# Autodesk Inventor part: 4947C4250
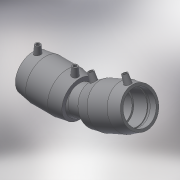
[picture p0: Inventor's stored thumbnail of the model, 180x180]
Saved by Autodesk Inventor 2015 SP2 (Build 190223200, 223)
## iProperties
Created: 2017-06
Part Number: 4947C4250
Material: Generic
Description: PLASSON ADJUSTABLE ELBOW 250
Document SubType Name: Modeling
Designer: KIM
Mass: 55.0731 g
Surface Area: 148.067 cm^2
Volume: 55.0731 cm^3
Density: 1 g/cm^3
Appearance: Default
Author: KIM
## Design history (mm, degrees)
derived "4947C4.ipt"
feature "Solid1::4947C4.ipt"
tag "TaggingFeature1"
body "Solid1"
other parameters: "d0" = 257.6, "d2" = 312, "d3" = 123, "d4" = 61.5, "d5" = 280.8, "d8" = 168 deg, "d10" = 49.2, "d11" = 16.4, "d29" = 156, "d30" = 15, "d31" = 103.04, "d34" = 5 deg, "d41" = 4, "d42" = 14, "d43" = 0, "d48" = 225, "d49" = 24 deg, "d50" = 644, "d51" = 78 deg, "d52" = 90 deg, "d55" = 67.3, "d57" = 168 deg, "d58" = 13.46, "d60" = 78.03467, "d62" = 3, "d63" = 0, "L_" = 644, "L_1" = 123, "D_" = 312, "A_" = 156, "d_2" = 12, "L_0" = 148, "d54" = 134.6, "d59" = 260.11555
